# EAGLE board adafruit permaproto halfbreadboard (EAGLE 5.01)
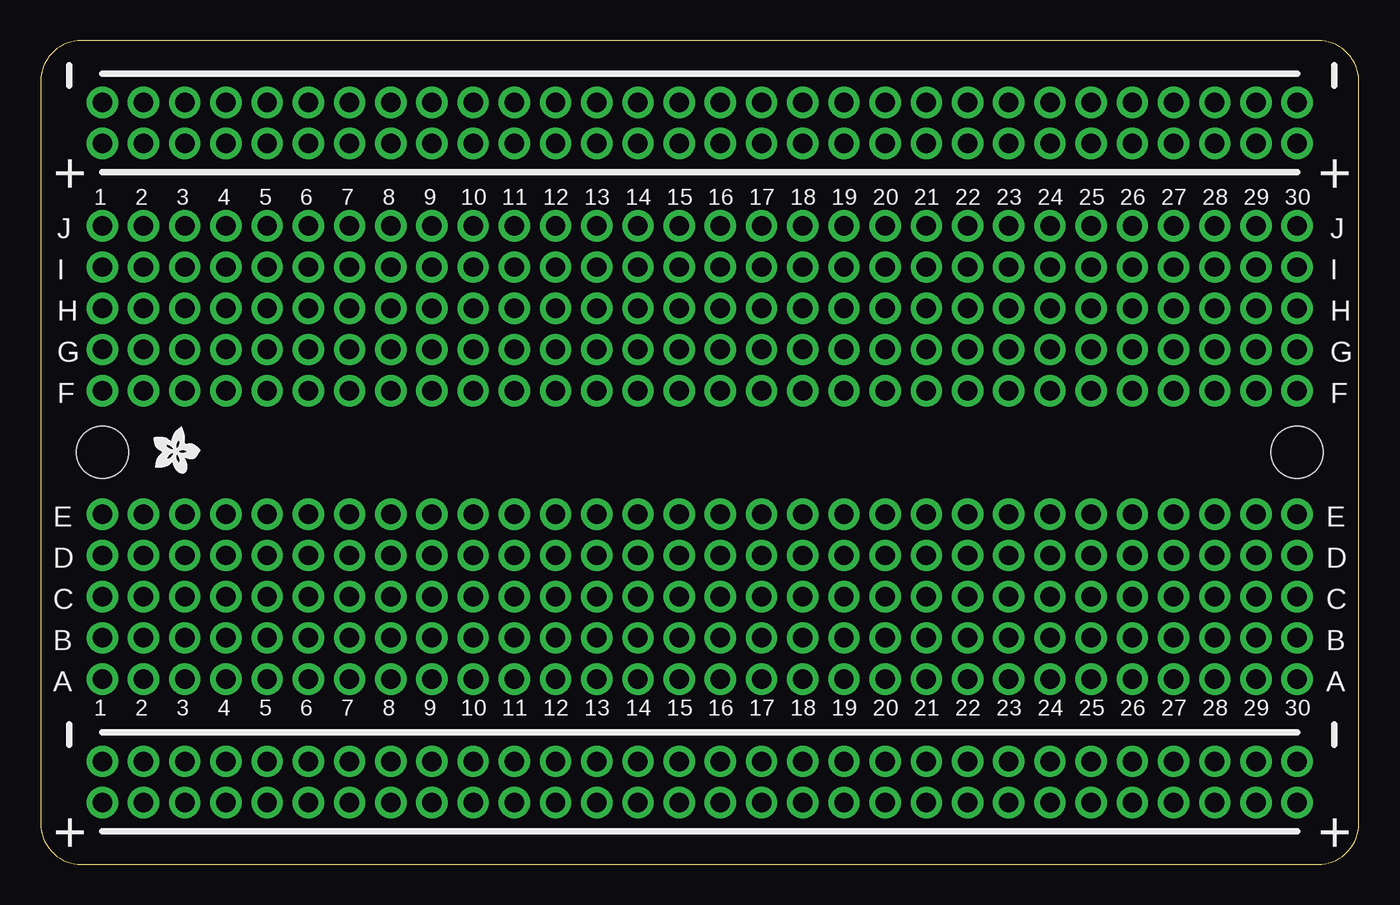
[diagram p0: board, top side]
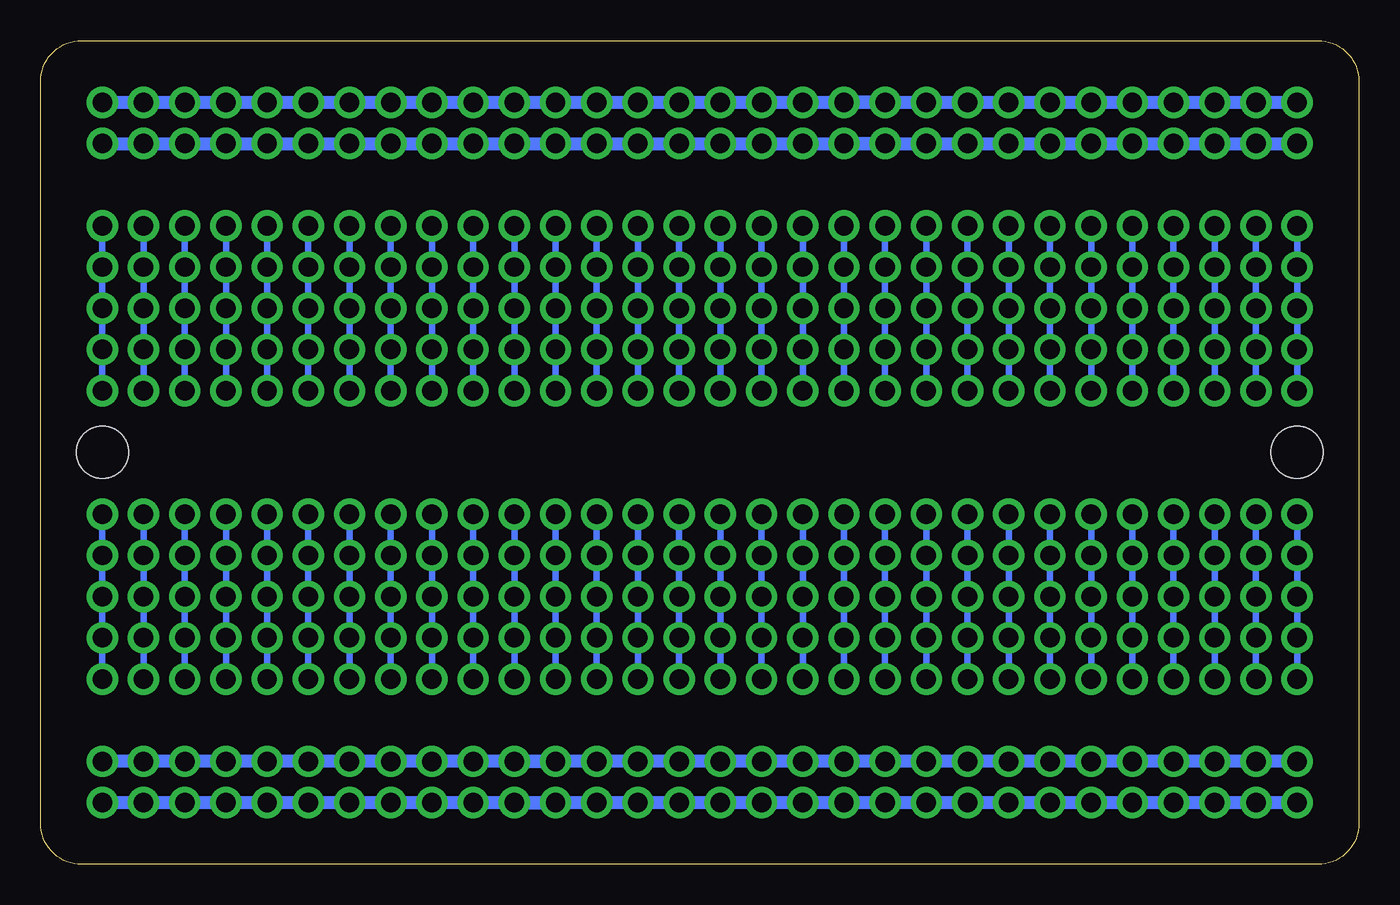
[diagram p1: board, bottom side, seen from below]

Size 81.28 x 50.8 mm. Coordinates in mm from the lower left corner, seen from the top.
Outline: 2.54,50.8 arc90 0,48.26 0,2.54 arc90 2.54,0 78.74,0 arc90 81.28,2.54 81.28,48.26 arc90 78.74,50.8 2.54,50.8
Copper layers (1*16): Top 0.035mm / dielectric 1.5mm / Bottom 0.035mm
Design rules "default": minimum track width 10mil, minimum drill 24mil, track to track 8mil, track to pad 8mil, pad to pad 8mil, via to via 8mil, smd to smd 8mil, copper to edge 40mil, drill to drill 8mil, minimum pad ring 10mil, minimum via ring 8mil, stop-mask expansion 4mil, vias tented up to drill 0mil, thermal gap 10mil
Holes 3.2 mm at 3.81,25.4 77.47,25.4

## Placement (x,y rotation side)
U$1  [ADAFRUIT200MIL]  8.38,25.65 270 top

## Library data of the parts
U$1 = adafruit

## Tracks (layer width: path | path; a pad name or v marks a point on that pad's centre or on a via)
N$1  (via drill 1.2 pad 1.93)
  Bottom 0.406: v3.81,21.59 v3.81,19.05 v3.81,16.51 v3.81,13.97 v3.81,11.43
N$2  (via drill 1.2 pad 1.93)
  Bottom 0.406: v6.35,11.43 v6.35,13.97 v6.35,16.51 v6.35,19.05 v6.35,21.59
N$3  (via drill 1.2 pad 1.93)
  Bottom 0.406: v8.89,21.59 v8.89,19.05 v8.89,16.51 v8.89,13.97 v8.89,11.43
N$4  (via drill 1.2 pad 1.93)
  Bottom 0.406: v11.43,11.43 v11.43,13.97 v11.43,16.51 v11.43,19.05 v11.43,21.59
N$5  (via drill 1.2 pad 1.93)
  Bottom 0.406: v13.97,21.59 v13.97,19.05 v13.97,16.51 v13.97,13.97 v13.97,11.43
N$6  (via drill 1.2 pad 1.93)
  Bottom 0.406: v16.51,11.43 v16.51,13.97 v16.51,16.51 v16.51,19.05 v16.51,21.59
N$7  (via drill 1.2 pad 1.93)
  Bottom 0.406: v21.59,11.43 v21.59,13.97 v21.59,16.51 v21.59,19.05 v21.59,21.59
N$8  (via drill 1.2 pad 1.93)
  Bottom 0.406: v19.05,21.59 v19.05,19.05 v19.05,16.51 v19.05,13.97 v19.05,11.43
N$9  (via drill 1.2 pad 1.93)
  Bottom 0.406: v24.13,21.59 v24.13,19.05 v24.13,16.51 v24.13,13.97 v24.13,11.43
N$10  (via drill 1.2 pad 1.93)
  Bottom 0.406: v26.67,21.59 v26.67,19.05 v26.67,16.51 v26.67,13.97 v26.67,11.43
N$11  (via drill 1.2 pad 1.93)
  Bottom 0.406: v29.21,21.59 v29.21,19.05 v29.21,16.51 v29.21,13.97 v29.21,11.43
N$12  (via drill 1.2 pad 1.93)
  Bottom 0.406: v31.75,11.43 v31.75,13.97 v31.75,16.51 v31.75,19.05 v31.75,21.59
N$13  (via drill 1.2 pad 1.93)
  Bottom 0.406: v34.29,21.59 v34.29,19.05 v34.29,16.51 v34.29,13.97 v34.29,11.43
N$14  (via drill 1.2 pad 1.93)
  Bottom 0.406: v36.83,11.43 v36.83,13.97 v36.83,16.51 v36.83,19.05 v36.83,21.59
N$15  (via drill 1.2 pad 1.93)
  Bottom 0.406: v39.37,11.43 v39.37,13.97 v39.37,16.51 | v39.37,16.51 v39.37,19.05 | v39.37,19.05 v39.37,21.59 | v39.37,16.51 v39.37,19.05
N$16  (via drill 1.2 pad 1.93)
  Bottom 0.406: v41.91,21.59 v41.91,19.05 v41.91,16.51 v41.91,13.97 v41.91,11.43
N$17  (via drill 1.2 pad 1.93)
  Bottom 0.406: v46.99,21.59 v46.99,19.05 v46.99,16.51 v46.99,13.97 v46.99,11.43
N$18  (via drill 1.2 pad 1.93)
  Bottom 0.406: v44.45,11.43 v44.45,13.97 v44.45,16.51 v44.45,19.05 v44.45,21.59
N$19  (via drill 1.2 pad 1.93)
  Bottom 0.406: v49.53,21.59 v49.53,19.05 v49.53,16.51 v49.53,13.97 v49.53,11.43
N$20  (via drill 1.2 pad 1.93)
  Bottom 0.406: v52.07,11.43 v52.07,13.97 v52.07,16.51 v52.07,19.05 v52.07,21.59
N$21  (via drill 1.2 pad 1.93)
  Bottom 0.406: v57.15,11.43 v57.15,13.97 v57.15,16.51 v57.15,19.05 v57.15,21.59
N$22  (via drill 1.2 pad 1.93)
  Bottom 0.406: v54.61,21.59 v54.61,19.05 v54.61,16.51 v54.61,13.97 v54.61,11.43
N$23  (via drill 1.2 pad 1.93)
  Bottom 0.406: v59.69,21.59 v59.69,19.05 v59.69,16.51 v59.69,13.97 v59.69,11.43
N$24  (via drill 1.2 pad 1.93)
  Bottom 0.406: v62.23,11.43 v62.23,13.97 v62.23,16.51 v62.23,19.05 v62.23,21.59
N$25  (via drill 1.2 pad 1.93)
  Bottom 0.406: v64.77,21.59 v64.77,19.05 v64.77,16.51 v64.77,13.97 v64.77,11.43
N$26  (via drill 1.2 pad 1.93)
  Bottom 0.406: v67.31,11.43 v67.31,13.97 v67.31,16.51 v67.31,19.05 v67.31,21.59
N$27  (via drill 1.2 pad 1.93)
  Bottom 0.406: v72.39,21.59 v72.39,19.05 v72.39,16.51 v72.39,13.97 v72.39,11.43
N$28  (via drill 1.2 pad 1.93)
  Bottom 0.406: v69.85,11.43 v69.85,13.97 v69.85,16.51 v69.85,19.05 v69.85,21.59
N$29  (via drill 1.2 pad 1.93)
  Bottom 0.406: v74.93,21.59 v74.93,19.05 v74.93,16.51 v74.93,13.97 v74.93,11.43
N$30  (via drill 1.2 pad 1.93)
  Bottom 0.406: v77.47,11.43 v77.47,13.97 v77.47,16.51 v77.47,19.05 v77.47,21.59
N$31  (via drill 1.2 pad 1.93)
  Bottom 0.813: v3.81,6.35 v6.35,6.35 v8.89,6.35 v11.43,6.35 v13.97,6.35 v16.51,6.35 v19.05,6.35 v21.59,6.35 v24.13,6.35 v26.67,6.35 v29.21,6.35 v31.75,6.35 v34.29,6.35 v36.83,6.35 v39.37,6.35 v41.91,6.35 v44.45,6.35 v46.99,6.35 v49.53,6.35 | v49.53,6.35 v52.07,6.35 | v52.07,6.35 v54.61,6.35 v57.15,6.35 v59.69,6.35 v62.23,6.35 v64.77,6.35 v67.31,6.35 | v67.31,6.35 v69.85,6.35 | v69.85,6.35 v72.39,6.35 v74.93,6.35 v77.47,6.35 | v67.31,6.35 v69.85,6.35 | v52.07,6.35 v49.53,6.35
N$32  (via drill 1.2 pad 1.93)
  Bottom 0.813: v3.81,3.81 v6.35,3.81 v8.89,3.81 v11.43,3.81 v13.97,3.81 v16.51,3.81 v19.05,3.81 v21.59,3.81 v24.13,3.81 v26.67,3.81 v29.21,3.81 v31.75,3.81 v34.29,3.81 v36.83,3.81 v39.37,3.81 v41.91,3.81 v44.45,3.81 v46.99,3.81 v49.53,3.81 | v49.53,3.81 v52.07,3.81 | v52.07,3.81 v54.61,3.81 v57.15,3.81 v59.69,3.81 v62.23,3.81 v64.77,3.81 v67.31,3.81 | v67.31,3.81 v69.85,3.81 | v69.85,3.81 v72.39,3.81 v74.93,3.81 v77.47,3.81 | v67.31,3.81 v69.85,3.81 | v52.07,3.81 v49.53,3.81
N$33  (via drill 1.2 pad 1.93)
  Bottom 0.406: v77.47,29.21 v77.47,31.75 v77.47,34.29 v77.47,36.83 v77.47,39.37
N$34  (via drill 1.2 pad 1.93)
  Bottom 0.406: v74.93,39.37 v74.93,36.83 v74.93,34.29 v74.93,31.75 v74.93,29.21
N$35  (via drill 1.2 pad 1.93)
  Bottom 0.406: v72.39,29.21 v72.39,31.75 v72.39,34.29 v72.39,36.83 v72.39,39.37
N$36  (via drill 1.2 pad 1.93)
  Bottom 0.406: v69.85,39.37 v69.85,36.83 v69.85,34.29 v69.85,31.75 v69.85,29.21
N$37  (via drill 1.2 pad 1.93)
  Bottom 0.406: v67.31,29.21 v67.31,31.75 v67.31,34.29 v67.31,36.83 v67.31,39.37
N$38  (via drill 1.2 pad 1.93)
  Bottom 0.406: v64.77,39.37 v64.77,36.83 v64.77,34.29 v64.77,31.75 v64.77,29.21
N$39  (via drill 1.2 pad 1.93)
  Bottom 0.406: v59.69,39.37 v59.69,36.83 v59.69,34.29 v59.69,31.75 v59.69,29.21
N$40  (via drill 1.2 pad 1.93)
  Bottom 0.406: v62.23,29.21 v62.23,31.75 v62.23,34.29 v62.23,36.83 v62.23,39.37
N$41  (via drill 1.2 pad 1.93)
  Bottom 0.406: v57.15,29.21 v57.15,31.75 v57.15,34.29 v57.15,36.83 v57.15,39.37
N$42  (via drill 1.2 pad 1.93)
  Bottom 0.406: v54.61,29.21 v54.61,31.75 v54.61,34.29 v54.61,36.83 v54.61,39.37
N$43  (via drill 1.2 pad 1.93)
  Bottom 0.406: v52.07,29.21 v52.07,31.75 v52.07,34.29 v52.07,36.83 v52.07,39.37
N$44  (via drill 1.2 pad 1.93)
  Bottom 0.406: v49.53,39.37 v49.53,36.83 v49.53,34.29 v49.53,31.75 v49.53,29.21
N$45  (via drill 1.2 pad 1.93)
  Bottom 0.406: v46.99,29.21 v46.99,31.75 v46.99,34.29 v46.99,36.83 v46.99,39.37
N$46  (via drill 1.2 pad 1.93)
  Bottom 0.406: v44.45,39.37 v44.45,36.83 v44.45,34.29 v44.45,31.75 v44.45,29.21
N$47  (via drill 1.2 pad 1.93)
  Bottom 0.406: v41.91,39.37 v41.91,36.83 v41.91,34.29 | v41.91,34.29 v41.91,31.75 | v41.91,31.75 v41.91,29.21 | v41.91,34.29 v41.91,31.75
N$48  (via drill 1.2 pad 1.93)
  Bottom 0.406: v39.37,29.21 v39.37,31.75 v39.37,34.29 v39.37,36.83 v39.37,39.37
N$49  (via drill 1.2 pad 1.93)
  Bottom 0.406: v34.29,29.21 v34.29,31.75 v34.29,34.29 v34.29,36.83 v34.29,39.37
N$50  (via drill 1.2 pad 1.93)
  Bottom 0.406: v36.83,39.37 v36.83,36.83 v36.83,34.29 v36.83,31.75 v36.83,29.21
N$51  (via drill 1.2 pad 1.93)
  Bottom 0.406: v31.75,29.21 v31.75,31.75 v31.75,34.29 v31.75,36.83 v31.75,39.37
N$52  (via drill 1.2 pad 1.93)
  Bottom 0.406: v29.21,39.37 v29.21,36.83 v29.21,34.29 v29.21,31.75 v29.21,29.21
N$53  (via drill 1.2 pad 1.93)
  Bottom 0.406: v24.13,39.37 v24.13,36.83 v24.13,34.29 v24.13,31.75 v24.13,29.21
N$54  (via drill 1.2 pad 1.93)
  Bottom 0.406: v26.67,29.21 v26.67,31.75 v26.67,34.29 v26.67,36.83 v26.67,39.37
N$55  (via drill 1.2 pad 1.93)
  Bottom 0.406: v21.59,29.21 v21.59,31.75 v21.59,34.29 v21.59,36.83 v21.59,39.37
N$56  (via drill 1.2 pad 1.93)
  Bottom 0.406: v19.05,39.37 v19.05,36.83 v19.05,34.29 v19.05,31.75 v19.05,29.21
N$57  (via drill 1.2 pad 1.93)
  Bottom 0.406: v16.51,29.21 v16.51,31.75 v16.51,34.29 v16.51,36.83 v16.51,39.37
N$58  (via drill 1.2 pad 1.93)
  Bottom 0.406: v13.97,39.37 v13.97,36.83 v13.97,34.29 v13.97,31.75 v13.97,29.21
N$59  (via drill 1.2 pad 1.93)
  Bottom 0.406: v8.89,29.21 v8.89,31.75 v8.89,34.29 v8.89,36.83 v8.89,39.37
N$60  (via drill 1.2 pad 1.93)
  Bottom 0.406: v11.43,39.37 v11.43,36.83 v11.43,34.29 v11.43,31.75 v11.43,29.21
N$61  (via drill 1.2 pad 1.93)
  Bottom 0.406: v6.35,29.21 v6.35,31.75 v6.35,34.29 v6.35,36.83 v6.35,39.37
N$62  (via drill 1.2 pad 1.93)
  Bottom 0.406: v3.81,39.37 v3.81,36.83 v3.81,34.29 v3.81,31.75 v3.81,29.21
N$63  (via drill 1.2 pad 1.93)
  Bottom 0.813: v77.47,44.45 v74.93,44.45 v72.39,44.45 v69.85,44.45 v67.31,44.45 v64.77,44.45 v62.23,44.45 v59.69,44.45 v57.15,44.45 v54.61,44.45 v52.07,44.45 v49.53,44.45 v46.99,44.45 v44.45,44.45 v41.91,44.45 v39.37,44.45 v36.83,44.45 v34.29,44.45 v31.75,44.45 | v31.75,44.45 v29.21,44.45 | v29.21,44.45 v26.67,44.45 v24.13,44.45 v21.59,44.45 v19.05,44.45 v16.51,44.45 v13.97,44.45 | v13.97,44.45 v11.43,44.45 | v11.43,44.45 v8.89,44.45 v6.35,44.45 v3.81,44.45 | v13.97,44.45 v11.43,44.45 | v29.21,44.45 v31.75,44.45
N$64  (via drill 1.2 pad 1.93)
  Bottom 0.813: v77.47,46.99 v74.93,46.99 v72.39,46.99 v69.85,46.99 v67.31,46.99 v64.77,46.99 v62.23,46.99 v59.69,46.99 v57.15,46.99 v54.61,46.99 v52.07,46.99 v49.53,46.99 v46.99,46.99 v44.45,46.99 v41.91,46.99 v39.37,46.99 v36.83,46.99 v34.29,46.99 v31.75,46.99 | v31.75,46.99 v29.21,46.99 | v29.21,46.99 v26.67,46.99 v24.13,46.99 v21.59,46.99 v19.05,46.99 v16.51,46.99 v13.97,46.99 | v13.97,46.99 v11.43,46.99 | v11.43,46.99 v8.89,46.99 v6.35,46.99 v3.81,46.99 | v13.97,46.99 v11.43,46.99 | v29.21,46.99 v31.75,46.99

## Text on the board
tPlace: 1 | 2 | 3 | 4 | 5 | 6 | 7 | 8 | 9 | 10 | 11 | 12 | 13 | 14 | 15 | 16 | 17 | 18 | 19 | 20 | 21 | 22 | 23 | 24 | 25 | 26 | 27 | 28 | 29 | 30 | J | J | I | I | H | H | G | G | F | F | E | E | D | D | C | C | B | B | A | A | 1 | 2 | 3 | 4 | 5 | 6 | 7 | 8 | 9 | 10 | 11 | 12 | 13 | 14 | 15 | 16 | 17 | 18 | 19 | 20 | 21 | 22 | 23 | 24 | 25 | 26 | 27 | 28 | 29 | 30
tDocu: Adafruit Perma-Proto 1/2 Sized Breadboard
tPlaceRed: + | + | + | +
